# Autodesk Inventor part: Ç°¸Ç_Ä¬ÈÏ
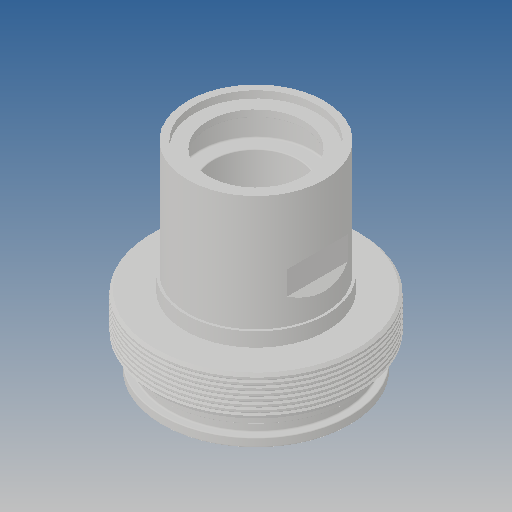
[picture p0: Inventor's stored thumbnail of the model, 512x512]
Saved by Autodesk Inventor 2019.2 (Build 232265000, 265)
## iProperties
Created: 2011-12
Part Number: Ç°¸Ç_Ä¬ÈÏ
Material: Ogólny
Document SubType Name: Modeling
Designer: CADENGINEERING4
Density: 1 g/cm^3
Appearance: Domyślna
Author: CADENGINEERING4
Revision Number: ÈÎºÎ
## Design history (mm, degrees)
feature "NONE"
node "Bryła1"
